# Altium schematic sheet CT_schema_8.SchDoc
size 274 x 160 mm
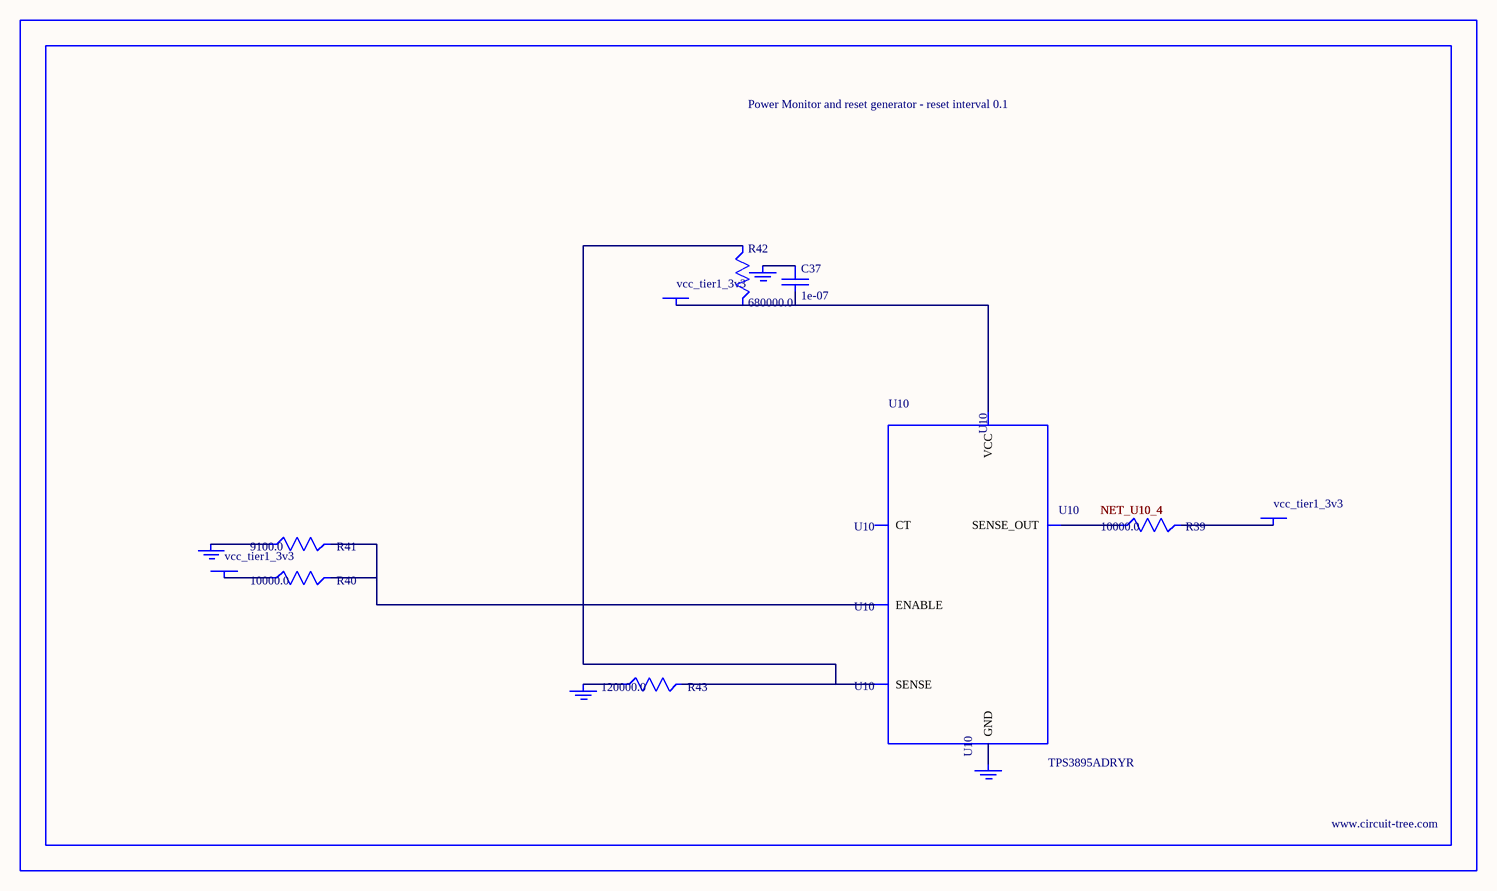
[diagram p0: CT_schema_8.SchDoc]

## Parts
BORDER7  (no value)
C37  1e-07  [C0402]
GND_INSTANCE_7_0  (no value)
GND_INSTANCE_7_1  (no value)
GND_INSTANCE_7_2  (no value)
GND_INSTANCE_7_3  (no value)
POWER_INSTANCE_7_0  vcc_tier1_3v3
POWER_INSTANCE_7_1  vcc_tier1_3v3
POWER_INSTANCE_7_2  vcc_tier1_3v3
R39  10000.0  [R0603]
R40  10000.0  [R0603]
R41  9100.0  [R0603]
R42  680000.0  [R0603]
R43  120000.0  [R0603]
U10  TPS3895ADRYR  [SON-6]

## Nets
NetC37_1: C37.1 GND_INSTANCE_7_2.0(GND)
NetC37_2: C37.2 POWER_INSTANCE_7_2.0(PWR) R42.2 U10.6(VCC)
NetGND_INSTANCE_7_0_0: GND_INSTANCE_7_0.0(GND) R41.1
NetGND_INSTANCE_7_1_0: GND_INSTANCE_7_1.0(GND) R43.1
NetGND_INSTANCE_7_3_0: GND_INSTANCE_7_3.0(GND) U10.2(GND)
NetPOWER_INSTANCE_7_0_0: POWER_INSTANCE_7_0.0(PWR) R40.1
NetPOWER_INSTANCE_7_1_0: POWER_INSTANCE_7_1.0(PWR) R39.2
NetR39_1: R39.1 U10.4(SENSE_OUT)
NetR40_2: R40.2 R41.2 U10.1(ENABLE)
NetR42_1: R42.1 R43.2 U10.3(SENSE)

Not connected (* = marked no-connect by the designer): U10 5(CT)

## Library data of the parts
BORDER7 = BORDER_PAGE7
C37 = C0402C104K3RACTU
GND_INSTANCE_7_0-GND_INSTANCE_7_3 = GND
POWER_INSTANCE_7_0-POWER_INSTANCE_7_2 = PWR
R39 R40 = RC0603JR-0710KL
R41 = RC0603JR-079K1L
R42 = RC0603JR-07680KL
R43 = RC0603JR-07120KL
